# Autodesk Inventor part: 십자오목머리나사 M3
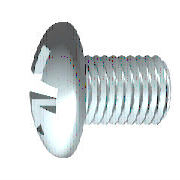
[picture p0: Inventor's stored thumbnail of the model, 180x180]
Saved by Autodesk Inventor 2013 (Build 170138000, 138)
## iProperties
Created: 2012-02
Part Number: 십자오목머리나사 M3
Material: 강철, 연강
Description: 십자 오목 머리 나사
Document SubType Name: Modeling
Standard: KS B 1023
Designer: mduedu
Standards Organization: KS
Language: ko-KR
Size Designation: A  M 3 x 6 - H
Categories: <MemberInstance><Categories><Category DisplayName="조임쇠" InternalName="e4da775c-781d-43d5-af7c-5136215cf5a6" Mnemonic="FSTN"><Category DisplayName="볼트" InternalN
Density: 7.86 g/cm^3
Mass: 0.662366 g
Surface Area: 1.40192 cm^2
Volume: 0.0842705 cm^3
IsCustomPart: 0
Author: mduedu
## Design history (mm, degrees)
workplane "Work Plane3"
sketch "스케치2"
  geometry: L1 (-3.72, 0)-(3.72, 0) reference; L2 (0, -3.72)-(0, 3.72) reference; L3 (0, 1.5)-(0, 0); L4 (0, 0)-(1.5, 0); L5 (0, 0)-(1.879, 1.879); L6 (0.253, 1.479)-(0.261, 0.456); L7 (1.479, 0.253)-(0.456, 0.261); L8 (0.253, -1.479)-(0.261, -0.456); L9 (1.479, -0.253)-(0.456, -0.261); L10 (-0.253, 1.479)-(-0.261, 0.456); L11 (-1.479, 0.253)-(-0.456, 0.261); L12 (-1.479, -0.253)-(-0.456, -0.261); L13 (-0.253, -1.479)-(-0.261, -0.456); A1 r 0.45 centre (0, 0) between (0.45, 0) and (0, 0.45); A2 r 1.5 centre (0, 0) between (1.5, 0) and (1.479, 0.253); A3 r 1.5 centre (0, 0) between (0.253, 1.479) and (0, 1.5); A4 r 1.5 centre (0, 0) between (1.479, 0.253) and (0.253, 1.479); A5 r 1.5 centre (0, 0) between (0, -1.5) and (0.253, -1.479); A6 r 1.5 centre (0, 0) between (0.253, -1.479) and (1.479, -0.253); A7 r 1.5 centre (0, 0) between (1.479, -0.253) and (1.5, 0); A8 r 1.5 centre (0, 0) between (-1.479, 0.253) and (-1.5, 0); A9 r 1.5 centre (0, 0) between (-0.253, 1.479) and (-1.479, 0.253); A10 r 1.5 centre (0, 0) between (0, 1.5) and (-0.253, 1.479); A11 r 1.5 centre (0, 0) between (-1.5, 0) and (-1.479, -0.253); A12 r 1.5 centre (0, 0) between (-1.479, -0.253) and (-0.253, -1.479); A13 r 1.5 centre (0, 0) between (-0.253, -1.479) and (0, -1.5); A14 r 0.525 centre (0, 0) between (0.525, 0) and (0, 0.525); A15 r 0.197 centre (0.457, 0.457) between (0.261, 0.456) and (0.456, 0.261); A16 r 0.197 centre (0.457, -0.457) between (0.456, -0.261) and (0.261, -0.456); A17 r 0.197 centre (-0.457, 0.457) between (-0.456, 0.261) and (-0.261, 0.456); A18 r 0.197 centre (-0.457, -0.457) between (-0.261, -0.456) and (-0.456, -0.261); 1 further point
  constraints: 38 point on circle, 22 end point, 19 symmetric about line, 18 centre point, 4 coincident, 3 collinear, 3 point on line, 3 tangent, 1 perpendicular, 21 other
  dimensions: "d4" = 45 deg angle of L5 L4; "d5" = 0.9 diameter of A1 (= 0.3 x SDM); "d6" = 3 diameter of A4 (= SDM); "d7" = 0.2525 distance from line of L6.start L3 (= 0.5 x SBR); "d14" = 1.05 diameter of A14 (= 0.35 x SDM)
extrude "슬롯" join sketch "스케치2" taper "d15" = 5 deg; stored distance "d54" = 10
revolve "절단부" stored, may be unused: angle "d56" = 90 deg
revolve "본체" stored, may be unused: angle "d18" = 90 deg
workplane "Work Plane1"
body "Solid1"
sketch "스케치1"
  geometry: L1 (6, 0)-(6, 1.5); L2 (6, 1.5)-(1, 1.5); L3 (3.962, 5.08)-(3.962, 5.08); L4 (-2.4, 0)-(-2.4, 2.59); L5 (-2.2, 1.4)-(-1.036, 0.82); L6 (-1.036, 0.82)-(-0.6, 0); L7 (-0.6, 0)-(6, 0); L8 (-4.305, 0)-(7.717, 0) reference; L9 (0, -1.016)-(0, 6.096) reference; L10 (-2.2, 1.4)-(-2.4, 1.5); L11 (-1.636, 2.657)-(-2.4, 2.59); L12 (-1.636, 2.657)-(0, 2.8); L13 (0, 2.8)-(0, 1.347); L14 (0, 1.347)-(0.693, 1.347); L15 (0.693, 1.347)-(1, 1.5); L16 (1, 1.5)-(0, 1.5); A1 r 5 centre (2.6, 0) between (-1.636, 2.657) and (-2.4, 0)
  constraints: 28 end point, 5 point on line, 4 collinear, 4 point on circle, 3 parallel, 2 perpendicular, 1 centre point, 1 horizontal, 1 tangent
  dimensions: "d1" = 3 diameter of L2 L7 (= GD); "d2" = 1.8 distance from line of L6.end L4 (= STI); "d11" = 3 diameter of L10.end L7 (= SDM); "d12" = 62 deg angle of L6 L7; "d13" = 26.5 deg angle of L5 L7; "d17" = 5.6 diameter of L12.end L7 (= KOD); "d19" = 5 deg angle of L12 L7 (= KEWI); "d20" = 2.4 distance between parallel lines of L4 L13 (= KOH); "d21" = 5 radius of A1 (= KR); "d23" = 2.6935 diameter of L14 L7 (= BDM); "d24" = 5 distance of L1.end L2.end (= GEL); "d25" = 0.30673 horizontal distance of L14.end L2.end (= GAL); "d28" = 6 distance between parallel lines of L1 L13 (= NLG)
fillet "모깎기1" dims "d29" = 1.2 (= RR)
fillet "모깎기2" dims "d16" = 0.101 (= 0.2 x SBR)
feature "스레드" dims "d8" = 5 (= GEL), "d9" = 0
chamfer "모따기1" distance "d26" = 0.30673 (= -0.5 x SPD + 0.5 x GD); stored, may be unused: second distance "d27" = 0.30683 (computed from GUL), angle "d78" = 45 deg
other parameters: "GD" = 3 (= NND) [user parameter; used in 2 equation terms], "NLG" = 6 [user parameter; used in 1 equation term], "GEL" = 5 [user parameter; used in 2 equation terms], "KOD" = 5.6 [user parameter; used in 1 equation term], "KOH" = 2.4 [user parameter; used in 2 equation terms], "SDM" = 3 [user parameter; used in 4 equation terms], "STI" = 1.8 [user parameter; used in 1 equation term], "SBR" = 0.505 [user parameter; used in 2 equation terms], "GAL" = 0.30673 (= 0.61345 x PTC) [user parameter; used in 1 equation term], "SPD" = 2.38655 (= NND - 1.2269 x PTC) [user parameter; used in 1 equation term], "KEWI" = 5 deg [user parameter; used in 1 equation term], "d3" = -2.4 (= -KOH), "d10" = 0, "KR" = 5 [user parameter; used in 1 equation term], "BDM" = 2.6935 [user parameter; used in 1 equation term], "GUL" = 0.30673 (= 0.61345 x PTC) [user parameter; used in 1 equation term], "RR" = 1.2 [user parameter; used in 1 equation term], "d79" = 0, "d80" = 0, "PTC" = 0.5 [user parameter; used in 5 equation terms], "THREADDIA" = 3 [user parameter; used in 1 equation term], "TOA" = 30 deg [user parameter], "NND" = 3 [user parameter; used in 2 equation terms], "GD1" = 2.38655 (= THREADDIA - 1.2269 x PTC) [user parameter]
